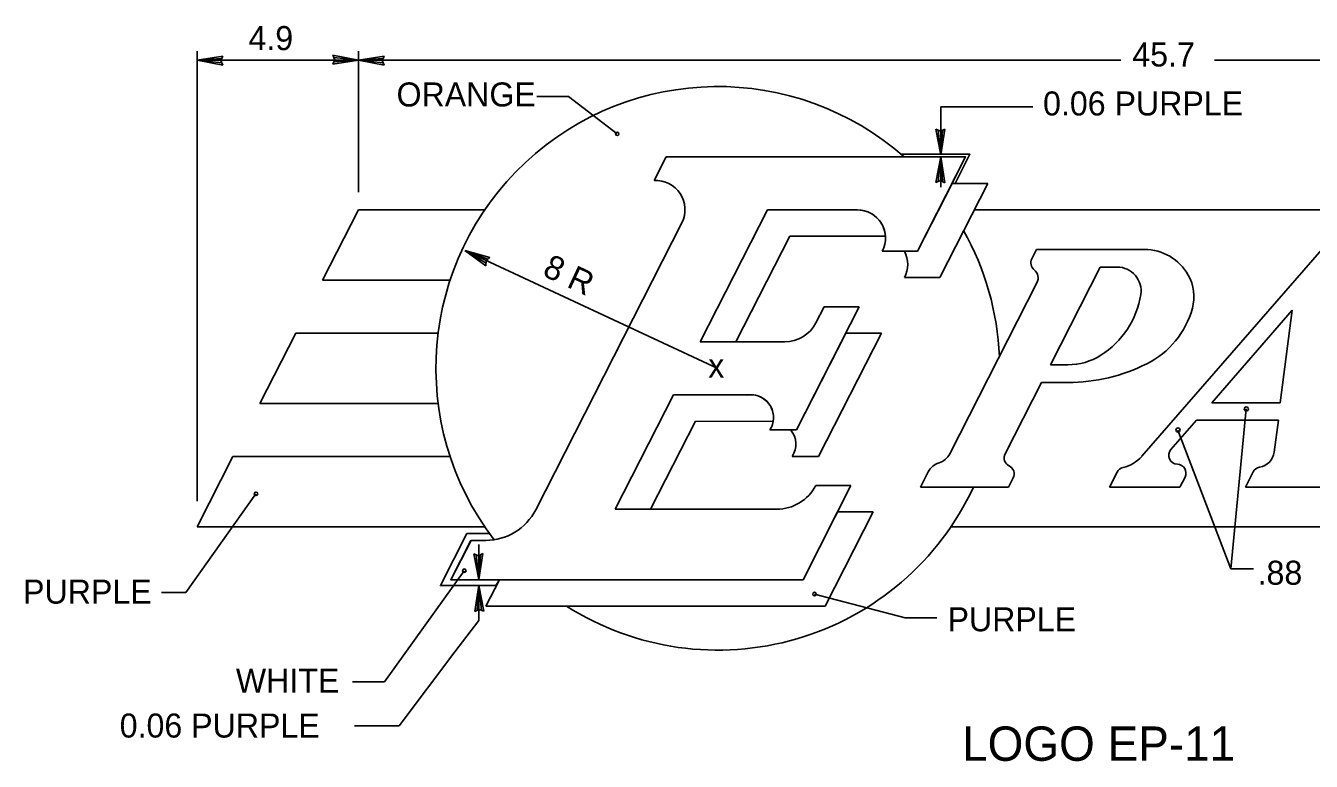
# Model space of a CAD drawing. Extents: x 10268197 to 10268826, y 2141503 to 2142677.
# Drawn here: x 10268493.16 to 10268525.45, y 2142363.97 to 2142382.45 of the extents above; entities that cross this region are included whole.
import ezdxf

# ---------------------------------------------------------------- set-up
doc = ezdxf.new("R2010")
doc.units = 0
for name, color, linetype in [('1', 7, 'Continuous'), ('Default', 7, 'Continuous'), ('TextDetails', 7, 'Continuous')]:
    doc.layers.add(name, color=color, linetype=linetype)

msp = doc.modelspace()

# ---------------------------------------------------------------- linework, layer by layer
at = {"layer": '1'}
for p, q in [((10268497.462, 2142370.51), (10268497.462, 2142381.807)), ((10268501.516, 2142378.267), (10268501.516, 2142381.807)), ((10268497.462, 2142381.586), (10268520.664, 2142381.586)), ((10268523.019, 2142381.586), (10268542.219, 2142381.586)), ((10268505.993, 2142380.675), (10268506.794, 2142380.675)), ((10268506.794, 2142380.675), (10268508.014, 2142379.732)), ((10268516.142, 2142380.409), (10268518.449, 2142380.409)), ((10268516.142, 2142379.238), (10268516.142, 2142380.409)), ((10268516.142, 2142378.395), (10268516.142, 2142379.158)), ((10268510.541, 2142373.843), (10268504.188, 2142376.806)), ((10268523.427, 2142368.805), (10268523.814, 2142372.823)), ((10268523.427, 2142368.805), (10268522.099, 2142372.294)), ((10268497.184, 2142368.214), (10268498.942, 2142370.693)), ((10268504.54, 2142369.421), (10268504.54, 2142368.541)), ((10268502.166, 2142365.97), (10268504.173, 2142368.759)), ((10268523.999, 2142368.805), (10268523.427, 2142368.805)), ((10268504.54, 2142368.384), (10268504.54, 2142367.511)), ((10268496.57, 2142368.214), (10268497.184, 2142368.214)), ((10268515.243, 2142367.579), (10268512.971, 2142368.173)), ((10268503.94, 2142366.719), (10268504.54, 2142367.511)), ((10268515.243, 2142367.579), (10268516.044, 2142367.579)), ((10268502.535, 2142364.865), (10268503.94, 2142366.719)), ((10268501.364, 2142365.97), (10268502.166, 2142365.97)), ((10268501.412, 2142364.865), (10268502.535, 2142364.865))]:
    msp.add_line(p, q, dxfattribs=at)
for centre, radius in [((10268508.014, 2142379.732), 0.0442), ((10268523.814, 2142372.823), 0.0518), ((10268522.099, 2142372.294), 0.0518), ((10268498.942, 2142370.692), 0.0442), ((10268504.173, 2142368.759), 0.0442), ((10268512.971, 2142368.172), 0.0442)]:
    msp.add_circle(centre, radius, dxfattribs=at)
at = {"layer": 'Default'}
for p, q in [((10268497.462, 2142381.586), (10268498.109, 2142381.688)), ((10268497.462, 2142381.586), (10268498.081, 2142381.629)), ((10268498.057, 2142381.576), (10268498.109, 2142381.688)), ((10268501.516, 2142381.586), (10268500.872, 2142381.711)), ((10268500.872, 2142381.711), (10268500.92, 2142381.596)), ((10268501.516, 2142381.586), (10268500.897, 2142381.651)), ((10268501.516, 2142381.586), (10268502.162, 2142381.688)), ((10268501.516, 2142381.586), (10268502.135, 2142381.629)), ((10268502.111, 2142381.576), (10268502.162, 2142381.688)), ((10268497.462, 2142381.586), (10268498.105, 2142381.461)), ((10268497.462, 2142381.586), (10268498.08, 2142381.521)), ((10268498.105, 2142381.461), (10268498.057, 2142381.576)), ((10268500.92, 2142381.596), (10268500.869, 2142381.483)), ((10268501.516, 2142381.586), (10268500.869, 2142381.483)), ((10268501.516, 2142381.586), (10268500.896, 2142381.542)), ((10268501.516, 2142381.586), (10268502.158, 2142381.461)), ((10268501.516, 2142381.586), (10268502.133, 2142381.521)), ((10268502.158, 2142381.461), (10268502.111, 2142381.576)), ((10268516.143, 2142379.207), (10268516.019, 2142379.849)), ((10268516.019, 2142379.849), (10268516.133, 2142379.802)), ((10268516.143, 2142379.207), (10268516.079, 2142379.825)), ((10268516.133, 2142379.802), (10268516.246, 2142379.854)), ((10268516.143, 2142379.207), (10268516.246, 2142379.854)), ((10268516.143, 2142379.207), (10268516.187, 2142379.826)), ((10268508.94, 2142378.559), (10268509.242, 2142379.152)), ((10268509.242, 2142379.152), (10268516.763, 2142379.152)), ((10268515.146, 2142379.219), (10268516.871, 2142379.219)), ((10268516.763, 2142379.152), (10268515.558, 2142376.787)), ((10268516.143, 2142379.154), (10268516.019, 2142378.511)), ((10268516.143, 2142379.154), (10268516.079, 2142378.536)), ((10268516.143, 2142379.154), (10268516.246, 2142378.507)), ((10268516.143, 2142379.154), (10268516.187, 2142378.535)), ((10268516.871, 2142379.219), (10268516.499, 2142378.489)), ((10268515.557, 2142376.784), (10268516.426, 2142378.489)), ((10268515.557, 2142376.784), (10268516.426, 2142378.489)), ((10268516.019, 2142378.511), (10268516.133, 2142378.558)), ((10268517.319, 2142378.489), (10268516.114, 2142376.123)), ((10268517.319, 2142378.489), (10268516.114, 2142376.123)), ((10268516.133, 2142378.558), (10268516.246, 2142378.507)), ((10268516.426, 2142378.489), (10268517.319, 2142378.489)), ((10268516.426, 2142378.489), (10268517.319, 2142378.489)), ((10268501.516, 2142377.825), (10268500.615, 2142376.055)), ((10268501.516, 2142377.825), (10268504.688, 2142377.825)), ((10268511.791, 2142377.825), (10268510.1, 2142374.507)), ((10268510.1, 2142374.507), (10268511.791, 2142377.825)), ((10268510.1, 2142374.507), (10268511.791, 2142377.825)), ((10268514.046, 2142377.825), (10268511.791, 2142377.825)), ((10268511.791, 2142377.825), (10268514.046, 2142377.825)), ((10268511.791, 2142377.825), (10268514.046, 2142377.825)), ((10268516.98, 2142377.825), (10268542.219, 2142377.825)), ((10268505.967, 2142370.292), (10268509.639, 2142377.5)), ((10268512.346, 2142377.162), (10268510.994, 2142374.507)), ((10268512.346, 2142377.162), (10268510.994, 2142374.507)), ((10268514.753, 2142377.162), (10268512.346, 2142377.162)), ((10268514.753, 2142377.162), (10268512.346, 2142377.162)), ((10268504.188, 2142376.806), (10268504.817, 2142376.625)), ((10268504.188, 2142376.806), (10268504.718, 2142376.421)), ((10268504.188, 2142376.806), (10268504.721, 2142376.486)), ((10268504.188, 2142376.806), (10268504.768, 2142376.583)), ((10268515.558, 2142376.787), (10268514.673, 2142376.787)), ((10268515.228, 2142376.784), (10268515.557, 2142376.784)), ((10268515.228, 2142376.784), (10268515.557, 2142376.784)), ((10268518.549, 2142376.829), (10268518.428, 2142376.594)), ((10268521.258, 2142376.829), (10268518.549, 2142376.829)), ((10268521.19, 2142371.634), (10268525.708, 2142376.829)), ((10268504.718, 2142376.421), (10268504.723, 2142376.545)), ((10268504.723, 2142376.545), (10268504.817, 2142376.625)), ((10268518.896, 2142373.932), (10268520.148, 2142376.387)), ((10268520.148, 2142376.387), (10268520.574, 2142376.387)), ((10268500.615, 2142376.055), (10268503.817, 2142376.055)), ((10268516.114, 2142376.123), (10268515.229, 2142376.123)), ((10268516.114, 2142376.123), (10268515.229, 2142376.123)), ((10268518.556, 2142375.993), (10268516.366, 2142371.694)), ((10268514.095, 2142375.392), (10268512.517, 2142372.295)), ((10268513.005, 2142374.99), (10268513.21, 2142375.392)), ((10268513.21, 2142375.392), (10268514.095, 2142375.392)), ((10268524.967, 2142375.304), (10268522.948, 2142372.98)), ((10268524.665, 2142372.98), (10268524.967, 2142375.304)), ((10268499.939, 2142374.728), (10268499.039, 2142372.958)), ((10268499.939, 2142374.728), (10268503.517, 2142374.728)), ((10268512.517, 2142372.295), (10268513.757, 2142374.728)), ((10268512.517, 2142372.295), (10268513.757, 2142374.728)), ((10268514.651, 2142374.728), (10268513.072, 2142371.631)), ((10268514.651, 2142374.728), (10268513.072, 2142371.631)), ((10268513.757, 2142374.728), (10268514.651, 2142374.728)), ((10268513.757, 2142374.728), (10268514.651, 2142374.728)), ((10268510.1, 2142374.507), (10268512.217, 2142374.507)), ((10268510.994, 2142374.507), (10268510.1, 2142374.507)), ((10268510.994, 2142374.507), (10268510.1, 2142374.507)), ((10268519.334, 2142373.932), (10268518.896, 2142373.932)), ((10268517.755, 2142371.694), (10268518.67, 2142373.489)), ((10268518.67, 2142373.489), (10268519.334, 2142373.489)), ((10268499.039, 2142372.958), (10268503.517, 2142372.958)), ((10268509.424, 2142373.18), (10268507.959, 2142370.304)), ((10268507.959, 2142370.304), (10268509.424, 2142373.18)), ((10268507.959, 2142370.304), (10268509.424, 2142373.18)), ((10268511.366, 2142373.18), (10268509.424, 2142373.18)), ((10268509.424, 2142373.18), (10268511.283, 2142373.174)), ((10268509.424, 2142373.18), (10268511.283, 2142373.174)), ((10268522.948, 2142372.98), (10268524.665, 2142372.98)), ((10268509.979, 2142372.514), (10268508.853, 2142370.304)), ((10268509.979, 2142372.514), (10268508.853, 2142370.304)), ((10268511.933, 2142372.508), (10268509.979, 2142372.514)), ((10268511.933, 2142372.508), (10268509.979, 2142372.514)), ((10268512.517, 2142372.295), (10268511.851, 2142372.295)), ((10268512.378, 2142372.295), (10268512.517, 2142372.295)), ((10268512.378, 2142372.295), (10268512.517, 2142372.295)), ((10268522.564, 2142372.538), (10268521.923, 2142371.801)), ((10268524.62, 2142372.538), (10268522.564, 2142372.538)), ((10268524.515, 2142371.738), (10268524.62, 2142372.538)), ((10268498.363, 2142371.631), (10268497.462, 2142369.861)), ((10268498.363, 2142371.631), (10268503.817, 2142371.631)), ((10268513.072, 2142371.631), (10268512.409, 2142371.631)), ((10268513.072, 2142371.631), (10268512.409, 2142371.631)), ((10268515.828, 2142371.247), (10268515.629, 2142370.856)), ((10268517.841, 2142370.856), (10268517.961, 2142371.093)), ((10268520.376, 2142370.856), (10268520.569, 2142371.235)), ((10268522.276, 2142371.112), (10268522.146, 2142370.856)), ((10268523.791, 2142370.856), (10268523.986, 2142371.241)), ((10268513.886, 2142370.899), (10268512.681, 2142368.534)), ((10268513.001, 2142370.899), (10268513.886, 2142370.899)), ((10268515.629, 2142370.856), (10268517.841, 2142370.856)), ((10268522.146, 2142370.856), (10268520.376, 2142370.856)), ((10268526.003, 2142370.856), (10268523.791, 2142370.856)), ((10268507.959, 2142370.304), (10268512.019, 2142370.304)), ((10268508.853, 2142370.304), (10268507.959, 2142370.304)), ((10268508.853, 2142370.304), (10268507.959, 2142370.304)), ((10268512.681, 2142368.534), (10268513.547, 2142370.236)), ((10268512.681, 2142368.534), (10268513.547, 2142370.236)), ((10268514.442, 2142370.236), (10268513.236, 2142367.871)), ((10268514.442, 2142370.236), (10268513.236, 2142367.871)), ((10268513.547, 2142370.236), (10268514.442, 2142370.236)), ((10268513.547, 2142370.236), (10268514.442, 2142370.236)), ((10268497.462, 2142369.861), (10268504.688, 2142369.861)), ((10268504.241, 2142369.692), (10268503.576, 2142368.384)), ((10268504.241, 2142369.692), (10268504.806, 2142369.692)), ((10268516.394, 2142369.861), (10268538.161, 2142369.861)), ((10268503.832, 2142368.534), (10268504.334, 2142369.519)), ((10268504.334, 2142369.519), (10268504.706, 2142369.519)), ((10268504.54, 2142368.541), (10268504.415, 2142369.184)), ((10268504.415, 2142369.184), (10268504.53, 2142369.136)), ((10268504.54, 2142368.541), (10268504.475, 2142369.159)), ((10268504.53, 2142369.136), (10268504.643, 2142369.188)), ((10268504.54, 2142368.541), (10268504.643, 2142369.188)), ((10268504.54, 2142368.541), (10268504.583, 2142369.16)), ((10268503.576, 2142368.384), (10268504.964, 2142368.384)), ((10268512.681, 2142368.534), (10268503.832, 2142368.534)), ((10268504.54, 2142368.384), (10268504.437, 2142367.737)), ((10268504.54, 2142368.384), (10268504.497, 2142367.764)), ((10268504.54, 2142368.384), (10268504.665, 2142367.741)), ((10268504.54, 2142368.384), (10268504.605, 2142367.765)), ((10268504.717, 2142367.871), (10268505.055, 2142368.534)), ((10268504.717, 2142367.871), (10268505.055, 2142368.534)), ((10268505.055, 2142368.534), (10268512.681, 2142368.534)), ((10268505.055, 2142368.534), (10268512.681, 2142368.534)), ((10268504.55, 2142367.788), (10268504.437, 2142367.737)), ((10268504.665, 2142367.741), (10268504.55, 2142367.788)), ((10268513.236, 2142367.871), (10268504.717, 2142367.871)), ((10268513.236, 2142367.871), (10268504.717, 2142367.871))]:
    msp.add_line(p, q, dxfattribs=at)
for points in [[(10268515.146, 2142379.219), (10268516.871, 2142379.219), (10268516.499, 2142378.489), (10268516.426, 2142378.489), (10268516.763, 2142379.152), (10268515.223, 2142379.152)], [(10268504.806, 2142369.692), (10268504.241, 2142369.692), (10268503.576, 2142368.384), (10268504.964, 2142368.384), (10268505.055, 2142368.534), (10268503.832, 2142368.534), (10268504.348, 2142369.519), (10268504.711, 2142369.519), (10268504.923, 2142369.536)]]:
    msp.add_lwpolyline(points, close=True, dxfattribs=at)
for centre, radius, start, end in [((10268510.541, 2142373.843), 7.079, 48.5904, 217.4727), ((10268508.988, 2142377.83), 0.73, 332.9998, 93.8045), ((10268514.046, 2142377.117), 0.708, 332.2089, 90), ((10268514.046, 2142377.117), 0.708, 3.5833, 90), ((10268514.046, 2142377.117), 0.708, 3.5833, 90), ((10268510.541, 2142373.843), 7.079, 2.4236, 29.2771), ((10268514.602, 2142376.453), 0.708, 332.2089, 27.9127), ((10268514.602, 2142376.453), 0.708, 332.2089, 27.9127), ((10268521.258, 2142375.568), 1.261, 29.4315, 90), ((10268518.625, 2142376.492), 0.221, 152.9784, 231.1602), ((10268518.32, 2142376.113), 0.265, 333.0027, 51.1602), ((10268520.574, 2142375.789), 0.597, 351.076, 90), ((10268521.393, 2142375.644), 1.106, 344.7074, 29.4315), ((10268518.978, 2142376.04), 2.212, 302.4206, 351.076), ((10268520.326, 2142375.936), 2.212, 296.6431, 344.7074), ((10268512.217, 2142375.391), 0.885, 270, 332.9883), ((10268519.334, 2142375.48), 1.548, 270, 302.4206), ((10268519.334, 2142377.913), 4.424, 270, 296.6431), ((10268511.366, 2142372.604), 0.575, 350.3502, 98.3344), ((10268511.366, 2142372.604), 0.575, 350.3502, 98.3344), ((10268511.366, 2142372.604), 0.575, 327.421, 90), ((10268511.925, 2142371.94), 0.575, 327.421, 37.9799), ((10268511.925, 2142371.94), 0.575, 327.421, 37.9799), ((10268515.972, 2142371.894), 0.442, 286.4317, 332.9959), ((10268517.953, 2142371.593), 0.221, 152.9884, 244.7832), ((10268520.523, 2142372.213), 0.885, 282.7162, 318.9966), ((10268522.09, 2142371.655), 0.221, 138.9824, 268.6869), ((10268524.077, 2142371.795), 0.442, 279.2397, 352.5632), ((10268516.222, 2142371.045), 0.442, 106.4317, 152.9742), ((10268517.764, 2142371.193), 0.221, 333.0239, 64.7832), ((10268520.766, 2142371.134), 0.221, 102.7162, 153.0239), ((10268522.079, 2142371.212), 0.221, 332.9784, 88.6869), ((10268524.183, 2142371.14), 0.221, 99.2397, 153.0239), ((10268510.541, 2142373.843), 7.079, 237.5383, 335.047), ((10268512.019, 2142371.409), 1.106, 270, 332.5096), ((10268504.706, 2142370.935), 1.416, 270, 332.9991)]:
    msp.add_arc(centre, radius, start, end, dxfattribs=at)

# ---------------------------------------------------------------- texts
at = {"layer": '1'}
for s, height, p in [('4.9', 0.6037, (10268498.753, 2142381.837)), ('45.7', 0.6037, (10268520.951, 2142381.425)), ('ORANGE', 0.6037, (10268502.472, 2142380.421)), ('0.06 PURPLE', 0.60368, (10268518.71, 2142380.195)), ('x', 0.604, (10268510.301, 2142373.607)), ('.88', 0.6037, (10268524.098, 2142368.407)), ('PURPLE', 0.6037, (10268493.092, 2142367.932)), ('PURPLE', 0.6037, (10268516.311, 2142367.237)), ('WHITE', 0.6037, (10268498.436, 2142365.699)), ('0.06 PURPLE', 0.60368, (10268495.519, 2142364.568))]:
    msp.add_text(s, height=height, dxfattribs=at).set_placement(p)
msp.add_text('8 R', height=0.6037, rotation=334.9991, dxfattribs=at).set_placement((10268506.109, 2142376.184))
at = {"layer": 'TextDetails'}
msp.add_text('LOGO EP-11', height=0.8624, dxfattribs=at).set_placement((10268516.677, 2142363.984))

doc.saveas('drawing.dxf')
